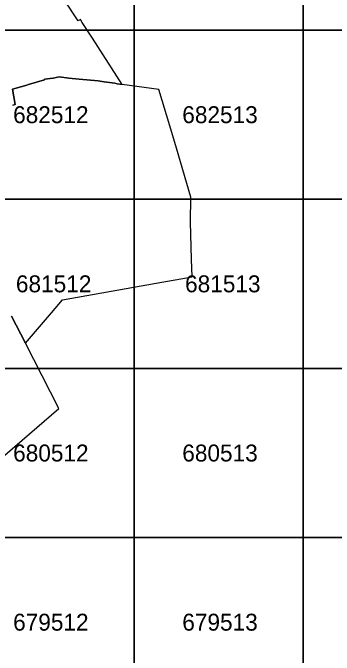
# Model space of a CAD drawing. Extents: x 25485000 to 25520000, y 6656775 to 6690000.
# Drawn here: x 25512283 to 25514183, y 6679305 to 6683102 of the extents above; entities that cross this region are included whole.
import ezdxf

# ---------------------------------------------------------------- set-up
doc = ezdxf.new("R2010")
doc.units = 0
doc.layers.add('Level 63', color=7, linetype='Continuous')

msp = doc.modelspace()

# ---------------------------------------------------------------- linework, layer by layer
at = {"layer": 'Level 63'}
for points in [[(25512000, 6683000), (25513000, 6683000), (25513000, 6684000), (25512000, 6684000)], [(25513000, 6683000), (25514000, 6683000), (25514000, 6684000), (25513000, 6684000)], [(25514000, 6683000), (25515000, 6683000), (25515000, 6684000), (25514000, 6684000)], [(25512000, 6682000), (25513000, 6682000), (25513000, 6683000), (25512000, 6683000)], [(25513000, 6682000), (25514000, 6682000), (25514000, 6683000), (25513000, 6683000)], [(25514000, 6682000), (25515000, 6682000), (25515000, 6683000), (25514000, 6683000)], [(25512000, 6681000), (25513000, 6681000), (25513000, 6682000), (25512000, 6682000)], [(25513000, 6681000), (25514000, 6681000), (25514000, 6682000), (25513000, 6682000)], [(25514000, 6681000), (25515000, 6681000), (25515000, 6682000), (25514000, 6682000)], [(25512000, 6680000), (25513000, 6680000), (25513000, 6681000), (25512000, 6681000)], [(25513000, 6680000), (25514000, 6680000), (25514000, 6681000), (25513000, 6681000)], [(25514000, 6680000), (25515000, 6680000), (25515000, 6681000), (25514000, 6681000)], [(25512000, 6679000), (25513000, 6679000), (25513000, 6680000), (25512000, 6680000)], [(25513000, 6679000), (25514000, 6679000), (25514000, 6680000), (25513000, 6680000)], [(25514000, 6679000), (25515000, 6679000), (25515000, 6680000), (25514000, 6680000)]]:
    msp.add_lwpolyline(points, close=True, dxfattribs=at)
for points in [[(25512282.5, 6682555.4), (25512296.9, 6682559.7), (25512281, 6682651), (25512331.5, 6682665.4), (25512365.7, 6682675.1), (25512376.4, 6682678.3), (25512423.5, 6682691.9), (25512471.4, 6682705.2), (25512470.2, 6682709), (25512521.8, 6682716.5), (25512557.7, 6682722.8), (25512613.7, 6682716.1), (25512675.8, 6682710.1), (25512788, 6682699.1), (25512823.6, 6682694.1), (25512886, 6682685.3), (25512900.9, 6682683.2), (25512930, 6682679.1), (25512753.8, 6682952.6), (25512693.6, 6683045.8), (25512683.2, 6683062.3), (25512669.9, 6683054), (25512585.5, 6683185.2)], [(25512276.1, 6681309.3), (25512357.7, 6681149.2), (25512452.5, 6681260.2), (25512511.7, 6681329.6), (25512576.5, 6681405.5), (25513131.1, 6681503.2), (25513343, 6681540.5), (25513339.7, 6681646.3), (25513333, 6681864.9), (25513336.2, 6682011.9), (25513250.2, 6682301.7), (25513211, 6682433.7), (25513147.2, 6682648.5), (25512930, 6682679.1), (25512900.9, 6682683.2), (25512886, 6682685.3), (25512823.6, 6682694.1), (25512788, 6682699.1), (25512675.8, 6682710.1), (25512613.7, 6682716.1), (25512557.7, 6682722.8), (25512521.8, 6682716.5), (25512470.2, 6682709), (25512471.4, 6682705.2), (25512423.5, 6682691.9), (25512376.4, 6682678.3), (25512365.7, 6682675.1), (25512331.5, 6682665.4), (25512281, 6682651), (25512296.9, 6682559.7), (25512282.5, 6682555.4)], [(25511325.7, 6679703.9), (25512554.5, 6680763), (25512357.7, 6681149.2), (25512276.1, 6681309.3)]]:
    msp.add_lwpolyline(points, dxfattribs=at)

# ---------------------------------------------------------------- texts
for s, p in [('682512', (25512285.1, 6682450)), ('682513', (25513285.1, 6682450)), ('681512', (25512301.6, 6681450)), ('681513', (25513301.6, 6681450)), ('680512', (25512285.1, 6680450)), ('680513', (25513285.1, 6680450)), ('679512', (25512285.1, 6679450)), ('679513', (25513285.1, 6679450))]:
    msp.add_text(s, height=100, dxfattribs=at).set_placement(p)

doc.saveas('drawing.dxf')
